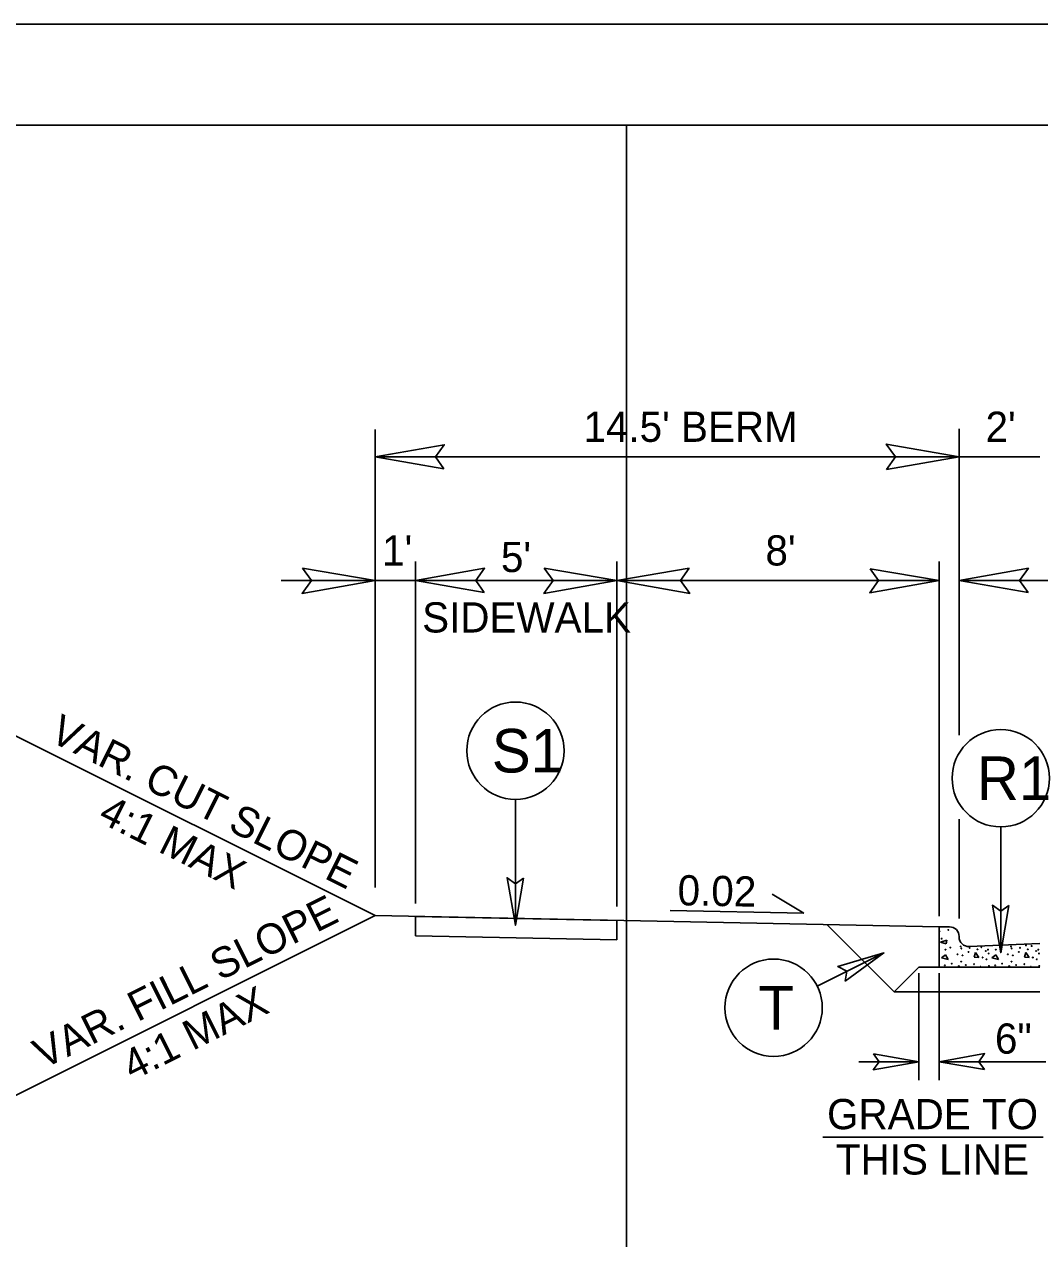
# Model space of a CAD drawing. Extents: x 1487909 to 1489267, y 497866 to 499814.
# Drawn here: x 1488960.01 to 1488985.22, y 498066.51 to 498096.65 of the extents above; entities that cross this region are included whole.
import ezdxf

# ---------------------------------------------------------------- set-up
doc = ezdxf.new("R2010")
doc.units = 0
for name, color, linetype in [('Prop Conc 4in Sidewalk', 7, 'Continuous'), ('Prop Dimension', 7, 'Continuous'), ('Prop Dimension Text', 7, 'Continuous'), ('Prop Shade Light', 7, 'Continuous'), ('Prop Terminator CELL', 7, 'Continuous'), ('Scratch_Level_1', 7, 'Continuous'), ('Sheet Plot Border Outside CELL', 7, 'Continuous'), ('Sheet Typical CELL', 7, 'Continuous'), ('Typical Curb CELL', 7, 'Continuous'), ('Typical Hinge Slope Arterial CELL', 7, 'Continuous'), ('Typical ID Circle CELL', 7, 'Continuous'), ('Typical Pavement Slope CELL', 7, 'Continuous'), ('Typical Pavement Slope Information CELL', 7, 'Continuous'), ('Typical Terminator CELL', 7, 'Continuous'), ('Typical Text ID Circle CELL', 7, 'Continuous')]:
    doc.layers.add(name, color=color, linetype=linetype)

msp = doc.modelspace()

# ---------------------------------------------------------------- linework, layer by layer
at = {"layer": 'Prop Conc 4in Sidewalk'}
for p, q in [((1488974.719, 498074.411), (1488969.719, 498074.511)), ((1488969.719, 498074.511), (1488969.719, 498074.03)), ((1488974.719, 498074.411), (1488974.719, 498073.93)), ((1488974.719, 498073.93), (1488969.719, 498074.03))]:
    msp.add_line(p, q, dxfattribs=at)
at = {"layer": 'Prop Dimension'}
for p, q in [((1488968.718, 498075.227), (1488968.718, 498086.596)), ((1488983.219, 498079.005), (1488983.219, 498086.616)), ((1488983.218, 498085.915), (1488968.718, 498085.915)), ((1488983.218, 498085.915), (1488985.218, 498085.915)), ((1488969.719, 498074.832), (1488969.719, 498083.317)), ((1488974.719, 498074.754), (1488974.719, 498083.317)), ((1488982.719, 498074.515), (1488982.719, 498083.317)), ((1488966.388, 498082.846), (1488968.719, 498082.846)), ((1488968.719, 498082.846), (1488969.719, 498082.846)), ((1488969.719, 498082.846), (1488974.719, 498082.846)), ((1488974.719, 498082.846), (1488982.719, 498082.846)), ((1488986.714, 498082.846), (1488983.219, 498082.846)), ((1488983.219, 498074.455), (1488983.219, 498076.925)), ((1488982.219, 498070.445), (1488982.219, 498073.098)), ((1488982.719, 498070.445), (1488982.719, 498073.098)), ((1488980.732, 498070.904), (1488982.219, 498070.904)), ((1488982.719, 498070.904), (1488985.367, 498070.904)), ((1488979.834, 498069.033), (1488985.307, 498069.033))]:
    msp.add_line(p, q, dxfattribs=at)
at = {"layer": 'Prop Shade Light'}
for p, q in [((1488974.719, 498074.411), (1488969.719, 498074.511)), ((1488969.719, 498074.511), (1488969.719, 498074.03)), ((1488974.719, 498073.93), (1488974.719, 498074.411)), ((1488969.719, 498074.03), (1488974.719, 498073.93))]:
    msp.add_line(p, q, dxfattribs=at)
at = {"layer": 'Prop Terminator CELL'}
for points in [[(1488970.428, 498085.621), (1488968.718, 498085.915), (1488970.438, 498086.219), (1488970.219, 498085.915)], [(1488981.418, 498085.605), (1488983.218, 498085.915), (1488981.408, 498086.235), (1488981.638, 498085.915)], [(1488966.919, 498083.156), (1488968.719, 498082.846), (1488966.909, 498082.526), (1488967.139, 498082.846)], [(1488971.429, 498082.552), (1488969.719, 498082.846), (1488971.438, 498083.15), (1488971.22, 498082.846)], [(1488972.919, 498083.156), (1488974.719, 498082.846), (1488972.909, 498082.526), (1488973.139, 498082.846)], [(1488976.519, 498083.156), (1488974.719, 498082.846), (1488976.529, 498082.526), (1488976.299, 498082.846)], [(1488984.929, 498082.552), (1488983.219, 498082.846), (1488984.938, 498083.15), (1488984.72, 498082.846)], [(1488981.009, 498083.141), (1488982.719, 498082.846), (1488980.999, 498082.542), (1488981.218, 498082.846)], [(1488981.094, 498071.098), (1488982.219, 498070.904), (1488981.088, 498070.704), (1488981.231, 498070.904)], [(1488983.844, 498070.71), (1488982.719, 498070.904), (1488983.85, 498071.104), (1488983.706, 498070.904)]]:
    msp.add_lwpolyline(points, close=True, dxfattribs=at)
at = {"layer": 'Scratch_Level_1'}
msp.add_line((1488974.964, 497989.154), (1488974.964, 498094.154), dxfattribs=at)
at = {"layer": 'Sheet Plot Border Outside CELL'}
msp.add_lwpolyline([(1489051.664, 498096.654), (1488883.264, 498096.654), (1488883.264, 497986.654), (1489051.664, 497986.654)], close=True, dxfattribs=at)
at = {"layer": 'Sheet Typical CELL'}
msp.add_lwpolyline([(1489049.964, 498094.154), (1488899.964, 498094.154), (1488899.964, 497989.154), (1489049.964, 497989.154)], close=True, dxfattribs=at)
at = {"layer": 'Typical Curb CELL'}
for p, q in [((1488982.719, 498073.251), (1488982.719, 498074.251)), ((1488982.719, 498074.251), (1488982.979, 498074.251)), ((1488982.755, 498073.873), (1488982.91, 498073.917)), ((1488982.893, 498073.827), (1488982.755, 498073.873)), ((1488982.91, 498073.917), (1488982.893, 498073.827)), ((1488983.219, 498074.001), (1488983.219, 498074.011)), ((1488985.219, 498073.834), (1488983.468, 498073.761)), ((1488982.881, 498073.554), (1488982.778, 498073.479)), ((1488982.944, 498073.439), (1488982.881, 498073.554)), ((1488983.623, 498073.61), (1488983.589, 498073.497)), ((1488983.708, 498073.49), (1488983.623, 498073.61)), ((1488984.13, 498073.554), (1488984.027, 498073.479)), ((1488984.193, 498073.439), (1488984.13, 498073.554)), ((1488984.872, 498073.61), (1488984.837, 498073.497)), ((1488984.958, 498073.49), (1488984.872, 498073.61)), ((1488982.719, 498073.251), (1488985.219, 498073.251)), ((1488982.778, 498073.479), (1488982.944, 498073.439)), ((1488983.589, 498073.497), (1488983.708, 498073.49)), ((1488984.027, 498073.479), (1488984.193, 498073.439)), ((1488984.837, 498073.497), (1488984.958, 498073.49))]:
    msp.add_line(p, q, dxfattribs=at)
for centre in [(1488982.732, 498074.141), (1488982.949, 498074.175), (1488982.784, 498073.958), (1488984.878, 498073.793), (1488982.881, 498073.685), (1488983.001, 498073.736), (1488983.178, 498073.571), (1488983.258, 498073.764), (1488983.275, 498073.714), (1488983.303, 498073.542), (1488983.452, 498073.628), (1488983.48, 498073.73), (1488983.674, 498073.691), (1488983.771, 498073.745), (1488983.88, 498073.651), (1488983.936, 498073.685), (1488983.953, 498073.588), (1488984.13, 498073.685), (1488984.25, 498073.736), (1488984.427, 498073.571), (1488984.507, 498073.764), (1488984.524, 498073.714), (1488984.552, 498073.542), (1488984.701, 498073.628), (1488984.729, 498073.73), (1488984.923, 498073.691), (1488985.02, 498073.775), (1488985.129, 498073.651), (1488985.185, 498073.685), (1488985.202, 498073.588), (1488982.864, 498073.297), (1488983.035, 498073.337), (1488983.212, 498073.274), (1488983.269, 498073.388), (1488983.383, 498073.303), (1488983.589, 498073.325), (1488983.748, 498073.257), (1488983.8, 498073.491), (1488983.896, 498073.445), (1488983.959, 498073.28), (1488984.113, 498073.297), (1488984.284, 498073.337), (1488984.461, 498073.274), (1488984.518, 498073.388), (1488984.632, 498073.303), (1488984.838, 498073.325), (1488984.997, 498073.257), (1488985.049, 498073.491), (1488985.145, 498073.445), (1488985.208, 498073.28)]:
    msp.add_circle(centre, 0.00802, dxfattribs=at)
for centre, start, end in [((1488982.979, 498074.011), 0, 90), ((1488983.458, 498074.001), 180, 272.3845)]:
    msp.add_arc(centre, 0.24, start, end, dxfattribs=at)
at = {"layer": 'Typical Hinge Slope Arterial CELL'}
for p, q in [((1488959.69, 498079.045), (1488968.719, 498074.531)), ((1488968.719, 498074.531), (1488959.69, 498070.016))]:
    msp.add_line(p, q, dxfattribs=at)
at = {"layer": 'Typical ID Circle CELL'}
for p, q in [((1488972.204, 498077.414), (1488972.204, 498074.291)), ((1488984.251, 498076.731), (1488984.251, 498073.608)), ((1488979.694, 498072.781), (1488981.351, 498073.605))]:
    msp.add_line(p, q, dxfattribs=at)
for centre in [(1488972.204, 498078.623), (1488984.251, 498077.94), (1488978.612, 498072.243)]:
    msp.add_circle(centre, 1.208, dxfattribs=at)
at = {"layer": 'Typical Pavement Slope CELL'}
for p, q in [((1488982.719, 498074.251), (1488968.719, 498074.531)), ((1488979.937, 498074.306), (1488981.606, 498072.638)), ((1488982.219, 498073.251), (1488981.606, 498072.638)), ((1488982.719, 498073.251), (1488982.219, 498073.251)), ((1488985.219, 498072.638), (1488981.606, 498072.638))]:
    msp.add_line(p, q, dxfattribs=at)
at = {"layer": 'Typical Pavement Slope Information CELL'}
for q in [(1488978.576, 498075.06), (1488976.043, 498074.653)]:
    msp.add_line((1488979.359, 498074.587), q, dxfattribs=at)
at = {"layer": 'Typical Terminator CELL'}
for points in [[(1488972.406, 498075.463), (1488972.204, 498074.291), (1488971.996, 498075.469), (1488972.204, 498075.32)], [(1488972.406, 498075.463), (1488972.204, 498074.291), (1488971.996, 498075.469), (1488972.204, 498075.32)], [(1488984.453, 498074.78), (1488984.251, 498073.608), (1488984.043, 498074.786), (1488984.251, 498074.636)], [(1488980.392, 498072.902), (1488981.351, 498073.605), (1488980.204, 498073.267), (1488980.43, 498073.147)]]:
    msp.add_lwpolyline(points, close=True, dxfattribs=at)

# ---------------------------------------------------------------- texts
at = {"layer": 'Prop Dimension Text'}
for s, p in [("14.5' BERM", (1488973.892, 498086.289)), ("2'", (1488983.874, 498086.289)), ("1'", (1488968.893, 498083.22)), ("5'", (1488971.843, 498083.057)), ("8'", (1488978.41, 498083.22)), ('SIDEWALK', (1488969.888, 498081.557)), ('6"', (1488984.107, 498071.103)), ('GRADE TO', (1488979.94, 498069.228)), ('THIS LINE', (1488980.159, 498068.103))]:
    msp.add_text(s, height=0.75, dxfattribs=at).set_placement(p)
at = {"layer": 'Typical Hinge Slope Arterial CELL'}
for s, rotation, p in [('VAR. CUT SLOPE', 333.4658, (1488960.601, 498078.879)), ('4:1 MAX', 333.4658, (1488961.812, 498076.877)), ('VAR. FILL SLOPE', 26.5342, (1488960.481, 498070.713)), ('4:1 MAX', 26.5342, (1488962.695, 498070.421))]:
    msp.add_text(s, height=0.75, rotation=rotation, dxfattribs=at).set_placement(p)
at = {"layer": 'Typical Pavement Slope Information CELL'}
msp.add_text('0.02', height=0.75, rotation=358.8543, dxfattribs=at).set_placement((1488976.223, 498074.788))
at = {"layer": 'Typical Text ID Circle CELL'}
for s, height, p in [('S1', 1.0817, (1488971.617, 498078.082)), ('R1', 1.0817, (1488983.657, 498077.399)), ('T', 1.082, (1488978.237, 498071.702))]:
    msp.add_text(s, height=height, dxfattribs=at).set_placement(p)

doc.saveas('drawing.dxf')
